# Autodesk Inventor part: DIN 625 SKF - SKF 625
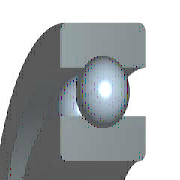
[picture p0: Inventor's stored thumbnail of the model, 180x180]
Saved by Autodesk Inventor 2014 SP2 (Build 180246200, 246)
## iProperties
IsCustomPart: 1
Created: 2013-02
Part Number: DIN 625 SKF - SKF 625
Material: Steel
Description: Single row ball bearings
Document SubType Name: Modeling
Standard: DIN 625
Designer: User
Standards Organization: DIN
Language: en-US
Size Designation: SKF 625
Categories: <MemberInstance><Categories><Category DisplayName="Shaft Parts" InternalName="7f7aeb1f-a693-4053-b835-cee3144e0d98" Mnemonic="SHFT"><Category DisplayName="Beari
Density: 7.85 g/cm^3
Appearance: Steel - Polished
Author: User
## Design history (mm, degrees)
node "Sketch1"
node "WorkPoint1"
node "WorkAxis1"
node "WorkPlane3"
node "WorkPlane4"
node "Sketch4"
node "WorkPoint2"
pattern_circular "PolarArray1" dims "d17" = 51.72727 (= msp_pocet), angle "d19" = 360 deg
fillet "Fillet1" dims "d20" = 0.3 (= r)
body "Solid1"
revolve "Revolution1" stored, may be unused: angle "d6" = 360 deg
revolve "Revolution2" stored, may be unused: angle "d10" = 360 deg
revolve "Revolution3" stored, may be unused: angle "d16" = 360 deg
sketch "Sketch2"
  geometry: L1 (2.5, 5)-(8, 5); L2 (2.5, 0)-(2.5, 5); L3 (8, 0)-(2.5, 0); L4 (8, 5)-(8, 0); L5 (0, 0)-(0, 20); L6 (0, 0)-(0, 20); L7 (-7.2, 0)-(43.2, 0) reference
  constraints: 12 end point, 3 vertical, 2 horizontal, 1 collinear, 1 other
  dimensions: "d1" = 5 vertical distance of L1.start L5 (= Diam); "d3" = 16 diameter of L1.end L5 (= DD); "d5" = 5 distance of L2.start L1.start (= msp_mdtd2)
sketch "Sketch3"
  geometry: L1 (6.24, 5)-(6.24, 3.82); L2 (4.26, 5)-(6.24, 5); L3 (4.26, 3.82)-(4.26, 5); L4 (4.26, 0)-(4.26, 1.18); L5 (6.24, 0)-(4.26, 0); L6 (6.24, 1.18)-(6.24, 0); L7 (8, 0)-(-8, 0) reference; L8 (8, 5)-(-8, 5) reference; L9 (0, -42.29)-(0, 61.29); L10 (0, 82.007)-(0, -63.007) reference; A1 r 1.65 centre (5.25, 2.5) between (6.24, 1.18) and (6.24, 3.82); A2 r 1.65 centre (5.25, 2.5) between (4.26, 3.82) and (4.26, 1.18)
  constraints: 14 end point, 4 collinear, 4 point on circle, 4 vertical, 2 centre point, 2 concentric, 2 horizontal, 2 point on line
  dimensions: "d9" = 3.3 diameter of A1 (= msp_mdtd6); "d21" = 4.26 distance between parallel lines of L9 L4 (= 0.5 x msp_d1); "d22" = 5.25 distance from line of L9 A1.centre (= 0.5 x msp_ds); "d23" = 6.24 distance between parallel lines of L9 L6 (= 0.5 x msp_dd1)
sketch "Sketch5"
  geometry: L1 (5.25, 0.85)-(5.25, 4.15); L2 (6.24, 0)-(-6.24, 0) reference; L3 (5.25, 0.85)-(5.25, 4.15); A1 r 1.65 centre (5.25, 2.5) between (5.25, 0.85) and (5.25, 4.15); A2 r 1.65 centre (5.25, 2.5) between (6.24, 1.18) and (6.24, 3.82) reference
  constraints: 4 end point, 2 point on circle, 1 centre point, 1 concentric, 1 vertical
  dimensions: "d13" = 0 horizontal distance of A1.centre L1.start; "d15" = 3.3001 diameter of A1 (computed from msp_mdtd6)
other parameters: "Diam" = 5 [user parameter; used in 3 equation terms], "DD" = 16 [user parameter; used in 3 equation terms], "B" = 5 [user parameter; used in 1 equation term], "r" = 0.3 [user parameter; used in 1 equation term], "msp_ds" = 10.5 (= 0.5 x Diam + 0.5 x DD) [user parameter; used in 5 equation terms], "msp_d0" = 3.3 (= -0.3 x Diam + 0.3 x DD) [user parameter; used in 4 equation terms], "msp_d1" = 8.52 (= msp_ds - 0.6 x msp_d0) [user parameter; used in 1 equation term], "msp_dd1" = 12.48 (= msp_ds + 0.6 x msp_d0) [user parameter; used in 1 equation term], "msp_pom" = 15.75 (= 1.5 x msp_ds) [user parameter; used in 1 equation term], "msp_mdtd2" = 5 (= B) [user parameter; used in 3 equation terms], "msp_mdtd4" = 10.5 (= msp_ds) [user parameter], "msp_mdtd6" = 3.3 (= msp_d0) [user parameter; used in 2 equation terms], "msp_mdtd7" = 2.5 (= 0.5 x msp_mdtd2) [user parameter], "msp_pocet" = 51.72727 (computed from msp_d0, msp_pom) [user parameter; used in 1 equation term], "d2" = 72 (derived), "d4" = 19 (derived), "d7" = 0, "d8" = 15.6 (derived), "d11" = -5 (computed from msp_mdtd2), "d12" = 0 (derived), "d14" = 15.6001 (derived)
